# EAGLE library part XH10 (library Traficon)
White connector 10pin connector for connecting Traficam to Eurobox interface
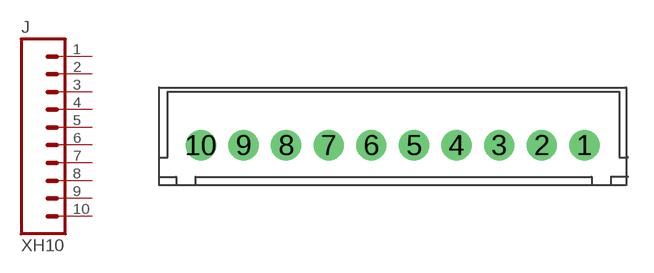
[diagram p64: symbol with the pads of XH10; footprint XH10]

Designator prefix J

## XH10  [XH10]
1  10  pas
2  9  pas
3  8  pas
4  7  pas
5  6  pas
6  5  pas
7  4  pas
8  3  pas
9  2  pas
10  1  pas

## Footprint XH10 (pad centres in mm)
drill 0.889 pad 1.778 round: 1 10.98,-0.19; 2 8.48,-0.19; 3 5.98,-0.19; 4 3.48,-0.19; 5 0.98,-0.19; 6 -1.52,-0.19; 7 -4.02,-0.19; 8 -6.52,-0.19; 9 -9.02,-0.19; 10 -11.52,-0.19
